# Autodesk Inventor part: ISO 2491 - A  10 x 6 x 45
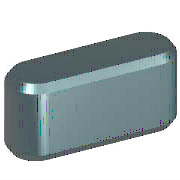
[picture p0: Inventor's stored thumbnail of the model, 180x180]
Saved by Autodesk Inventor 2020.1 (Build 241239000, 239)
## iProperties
Created: 2019-01
Part Number: ISO 2491 - A  10 x 6 x 45
Material: Stahl, weich
Description: Passfedern
Document SubType Name: Modeling
Standard: ISO 2491
Designer: lutzd
Standard Revision: First edition 1974-08-15
Standards Organization: ISO
Language: de-DE
Size Designation: A  10 x 6 x 45
Categories: <MemberInstance><Categories><Category DisplayName="Wellenteile" InternalName="7f7aeb1f-a693-4053-b835-cee3144e0d98" Mnemonic="SHFT"><Category DisplayName="Passf
Mass: 19.9012 g
Surface Area: 13.9335 cm^2
Volume: 2.53518 cm^3
Density: 7.85 g/cm^3
Appearance: Halbpoliert
IsCustomPart: 0
Author: lutzd
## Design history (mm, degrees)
workplane "Work Plane1"
workplane "Work Plane2"
sketch "Skizze1"
  geometry: L1 (5, 5)-(40, 5); L2 (40, -5)-(5, -5); L3 (0, 9.4)-(0, -7.4) reference; L4 (-5, 0)-(30, 0) reference; L5 (45, 0)-(45, 7); A1 r 5 centre (5, 0) between (5, 5) and (5, -5); A2 r 5 centre (40, 0) between (40, -5) and (40, 5)
  constraints: 6 end point, 5 point on circle, 4 tangent, 3 point on line, 2 centre point, 1 horizontal, 1 parallel, 1 perpendicular
  dimensions: "d0" = 5 radius of A1 (= 0.5 x PB); "d13" = 5 radius of A2 (= 0.5 x PB); "d14" = 45 distance between parallel lines of L5 L3 (= NLG)
extrude "Körper1" new body sketch "Skizze1" taper "d3" = 0 deg; stored distance "d4" = 10
workplane "Work Plane3"
body "Solid1"
chamfer "Fase1" distance "d8" = 0.6 (= PHH); stored, may be unused: second distance "d9" = 0.6 (= PHH), angle "d15" = 45 deg
other parameters: "d1" = -3.5 (= -PNT), "d2" = 2.5 (= PH - PNT), "NLG" = 45 [user parameter; used in 1 equation term], "PNT" = 3.5 [user parameter; used in 2 equation terms], "PH" = 6 [user parameter; used in 1 equation term], "PHH" = 0.6 [user parameter; used in 2 equation terms], "d10" = 0, "d16" = 0, "d17" = 0, "d18" = 0, "RR" = 0.25 [user parameter], "WDMAX" = 38 [user parameter], "PLB1" = 45 [user parameter], "PLB2" = 45 [user parameter], "PUEB" = 2.8 [user parameter]
